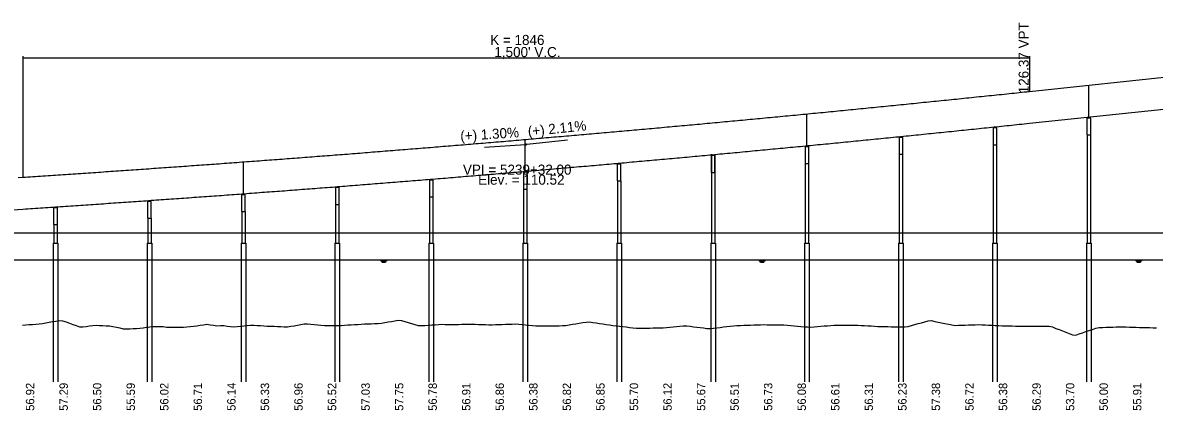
# Model space of a CAD drawing. Extents: x 2121671 to 2169879, y 557274 to 599957.
# Drawn here: x 2152750 to 2154437, y 595763 to 596342 of the extents above; entities that cross this region are included whole.
import ezdxf

# ---------------------------------------------------------------- set-up
doc = ezdxf.new("R2010")
doc.units = 0
for name, color, linetype in [('BR_CONCRETE', 7, 'Continuous'), ('BR_DETAILS', 7, 'Continuous'), ('BR_PRESTRESSED BEAM', 7, 'Continuous'), ('RD_DDB_GradeTX', 7, 'Continuous'), ('RD_DDB_Profile_Elev', 7, 'Continuous'), ('RD_DDB_Profile_EX', 7, 'Continuous'), ('RD_DDB_Profile_Lbl', 7, 'Continuous'), ('RD_DDB_Profile_PR', 7, 'Continuous'), ('RD_DDB_StripGrade', 7, 'Continuous'), ('RD_DDB_VCLbl', 7, 'Continuous')]:
    doc.layers.add(name, color=color, linetype=linetype)

msp = doc.modelspace()

# ---------------------------------------------------------------- linework, layer by layer
at = {"layer": 'BR_CONCRETE'}
for p, q in [((2154336.3, 596174.6), (2154336.3, 596013.1)), ((2154341.3, 596174.6), (2154341.3, 596013.1)), ((2154196.3, 596159.8), (2154196.3, 596013.1)), ((2154201.3, 596159.8), (2154201.3, 596013.1)), ((2153776.3, 596145.5), (2153776.3, 596013.1)), ((2153781.3, 596145.5), (2153781.3, 596013.1)), ((2153916.3, 596145.5), (2153916.3, 596013.1)), ((2153921.3, 596145.5), (2153921.3, 596013.1)), ((2154056.3, 596145.5), (2154056.3, 596013.1)), ((2154061.3, 596145.5), (2154061.3, 596013.1)), ((2153496.3, 596093.6), (2153496.3, 596013.1)), ((2153501.3, 596093.6), (2153501.3, 596013.1)), ((2153636.3, 596105.8), (2153636.3, 596013.1)), ((2153641.3, 596105.8), (2153641.3, 596013.1)), ((2153356.3, 596081.9), (2153356.3, 596013.1)), ((2153361.3, 596081.9), (2153361.3, 596013.1)), ((2153076.3, 596060.2), (2153076.3, 596013.1)), ((2153081.3, 596060.2), (2153081.3, 596013.1)), ((2153216.3, 596070.8), (2153216.3, 596013.1)), ((2153221.3, 596070.8), (2153221.3, 596013.1)), ((2152796.3, 596040.6), (2152796.3, 596013.1)), ((2152801.3, 596040.6), (2152801.3, 596013.1)), ((2152936.3, 596050.1), (2152936.3, 596013.1)), ((2152941.3, 596050.1), (2152941.3, 596013.1)), ((2152795.3, 596013.1), (2152795.3, 595805.8)), ((2152802.3, 596013.1), (2152802.3, 595805.8)), ((2152935.3, 596013.1), (2152935.3, 595805.8)), ((2152942.3, 596013.1), (2152942.3, 595805.8)), ((2153075.3, 596013.1), (2153075.3, 595805.8)), ((2153082.3, 596013.1), (2153082.3, 595805.8)), ((2153215.3, 596013.1), (2153215.3, 595805.8)), ((2153222.3, 596013.1), (2153222.3, 595805.8)), ((2153355.3, 596013.1), (2153355.3, 595805.8)), ((2153362.3, 596013.1), (2153362.3, 595805.8)), ((2153495.3, 596013.1), (2153495.3, 595805.8)), ((2153502.3, 596013.1), (2153502.3, 595805.8)), ((2153635.3, 596013.1), (2153635.3, 595805.8)), ((2153642.3, 596013.1), (2153642.3, 595805.8)), ((2153775.3, 596013.1), (2153775.3, 595805.8)), ((2153782.3, 596013.1), (2153782.3, 595805.8)), ((2153915.3, 596013.1), (2153915.3, 595805.8)), ((2153922.3, 596013.1), (2153922.3, 595805.8)), ((2154055.3, 596013.1), (2154055.3, 595805.8)), ((2154062.3, 596013.1), (2154062.3, 595805.8)), ((2154195.3, 596013.1), (2154195.3, 595805.8)), ((2154202.3, 596013.1), (2154202.3, 595805.8)), ((2154335.3, 596013.1), (2154335.3, 595805.8)), ((2154342.3, 596013.1), (2154342.3, 595805.8))]:
    msp.add_line(p, q, dxfattribs=at)
for points in [[(2154336.1, 596174.6), (2154341.6, 596174.6), (2154341.6, 596199.6), (2154336.1, 596199.6)], [(2154196.1, 596159.8), (2154201.6, 596159.8), (2154201.6, 596184.8), (2154196.1, 596184.8)], [(2153916.1, 596131.7), (2153921.6, 596131.7), (2153921.6, 596156.7), (2153916.1, 596156.7)], [(2154056.1, 596145.5), (2154061.6, 596145.5), (2154061.6, 596170.5), (2154056.1, 596170.5)], [(2153776.1, 596118.5), (2153781.6, 596118.5), (2153781.6, 596143.5), (2153776.1, 596143.5)], [(2153636.1, 596105.8), (2153641.6, 596105.8), (2153641.6, 596130.8), (2153636.1, 596130.8)], [(2153356.1, 596081.9), (2153361.6, 596081.9), (2153361.6, 596106.9), (2153356.1, 596106.9)], [(2153496.1, 596093.6), (2153501.6, 596093.6), (2153501.6, 596118.6), (2153496.1, 596118.6)], [(2153216.1, 596070.8), (2153221.6, 596070.8), (2153221.6, 596095.8), (2153216.1, 596095.8)], [(2152936.1, 596050.1), (2152941.6, 596050.1), (2152941.6, 596075.1), (2152936.1, 596075.1)], [(2153076.1, 596060.2), (2153081.6, 596060.2), (2153081.6, 596085.2), (2153076.1, 596085.2)], [(2152796.1, 596040.6), (2152801.6, 596040.6), (2152801.6, 596065.6), (2152796.1, 596065.6)]]:
    msp.add_lwpolyline(points, close=True, dxfattribs=at)
at = {"layer": 'BR_DETAILS'}
for points in [[(2154337.3, 596200.8), (2154338.3, 596200.8), (2154338.3, 596199.6), (2154337.3, 596199.6)], [(2154339.3, 596200.8), (2154340.3, 596200.8), (2154340.3, 596199.6), (2154339.3, 596199.6)], [(2154197.3, 596186.1), (2154198.3, 596186.1), (2154198.3, 596184.8), (2154197.3, 596184.8)], [(2154199.3, 596186.1), (2154200.3, 596186.1), (2154200.3, 596184.8), (2154199.3, 596184.8)], [(2153917.3, 596158), (2153918.3, 596158), (2153918.3, 596156.7), (2153917.3, 596156.7)], [(2153919.3, 596158), (2153920.3, 596158), (2153920.3, 596156.7), (2153919.3, 596156.7)], [(2154057.3, 596171.8), (2154058.3, 596171.8), (2154058.3, 596170.5), (2154057.3, 596170.5)], [(2154059.3, 596171.8), (2154060.3, 596171.8), (2154060.3, 596170.5), (2154059.3, 596170.5)], [(2153777.3, 596144.7), (2153778.3, 596144.7), (2153778.3, 596143.5), (2153777.3, 596143.5)], [(2153779.3, 596144.7), (2153780.3, 596144.7), (2153780.3, 596143.5), (2153779.3, 596143.5)], [(2153637.3, 596132), (2153638.3, 596132), (2153638.3, 596130.8), (2153637.3, 596130.8)], [(2153639.3, 596132), (2153640.3, 596132), (2153640.3, 596130.8), (2153639.3, 596130.8)], [(2153357.3, 596108.1), (2153358.3, 596108.1), (2153358.3, 596106.9), (2153357.3, 596106.9)], [(2153359.3, 596108.1), (2153360.3, 596108.1), (2153360.3, 596106.9), (2153359.3, 596106.9)], [(2153497.3, 596119.8), (2153498.3, 596119.8), (2153498.3, 596118.6), (2153497.3, 596118.6)], [(2153499.3, 596119.8), (2153500.3, 596119.8), (2153500.3, 596118.6), (2153499.3, 596118.6)], [(2153217.3, 596097), (2153218.3, 596097), (2153218.3, 596095.8), (2153217.3, 596095.8)], [(2153219.3, 596097), (2153220.3, 596097), (2153220.3, 596095.8), (2153219.3, 596095.8)], [(2152937.3, 596076.3), (2152938.3, 596076.3), (2152938.3, 596075.1), (2152937.3, 596075.1)], [(2152939.3, 596076.3), (2152940.3, 596076.3), (2152940.3, 596075.1), (2152939.3, 596075.1)], [(2153077.3, 596086.4), (2153078.3, 596086.4), (2153078.3, 596085.2), (2153077.3, 596085.2)], [(2153079.3, 596086.4), (2153080.3, 596086.4), (2153080.3, 596085.2), (2153079.3, 596085.2)], [(2152797.3, 596066.8), (2152798.3, 596066.8), (2152798.3, 596065.6), (2152797.3, 596065.6)], [(2152799.3, 596066.8), (2152800.3, 596066.8), (2152800.3, 596065.6), (2152799.3, 596065.6)]]:
    msp.add_lwpolyline(points, close=True, dxfattribs=at)
at = {"layer": 'BR_PRESTRESSED BEAM'}
for p, q in [((2154338.8, 596201), (2154338.8, 596248.5)), ((2154250.2, 596191.8), (2154543.2, 596222.7)), ((2153918.8, 596158.1), (2153918.8, 596205.6)), ((2153498.8, 596119.9), (2153498.8, 596167.4)), ((2153078.8, 596086.5), (2153078.8, 596134)), ((2152311.7, 596035.3), (2152750.2, 596063.8)), ((2152795.3, 596013.1), (2152802.3, 596013.1)), ((2152935.3, 596013.1), (2152942.3, 596013.1)), ((2153075.3, 596013.1), (2153082.3, 596013.1)), ((2153215.3, 596013.1), (2153222.3, 596013.1)), ((2153355.3, 596013.1), (2153362.3, 596013.1)), ((2153495.3, 596013.1), (2153502.3, 596013.1)), ((2153635.3, 596013.1), (2153642.3, 596013.1)), ((2153775.3, 596013.1), (2153782.3, 596013.1)), ((2153915.3, 596013.1), (2153922.3, 596013.1)), ((2154055.3, 596013.1), (2154062.3, 596013.1)), ((2154195.3, 596013.1), (2154202.3, 596013.1)), ((2154335.3, 596013.1), (2154342.3, 596013.1))]:
    msp.add_line(p, q, dxfattribs=at)
msp.add_spline([(2152750.2, 596063.8), (2152780.2, 596065.8), (2152810.2, 596067.8), (2152840.2, 596069.8), (2152870.2, 596071.8), (2152900.2, 596073.9), (2152930.2, 596076), (2152960.2, 596078.1), (2152990.2, 596080.2), (2153020.2, 596082.4), (2153050.2, 596084.5), (2153080.2, 596086.7), (2153110.2, 596089), (2153140.2, 596091.2), (2153170.2, 596093.5), (2153200.2, 596095.8), (2153230.2, 596098.1), (2153260.2, 596100.5), (2153290.2, 596102.9), (2153320.2, 596105.3), (2153350.2, 596107.7), (2153380.2, 596110.1), (2153410.2, 596112.6), (2153440.2, 596115.1), (2153470.2, 596117.6), (2153500.2, 596120.2), (2153530.2, 596122.8), (2153560.2, 596125.4), (2153590.2, 596128), (2153620.2, 596130.6), (2153650.2, 596133.3), (2153680.2, 596136), (2153710.2, 596138.7), (2153740.2, 596141.4), (2153770.2, 596144.2), (2153800.2, 596147), (2153830.2, 596149.8), (2153860.2, 596152.7), (2153890.2, 596155.5), (2153920.2, 596158.4), (2153950.2, 596161.3), (2153980.2, 596164.3), (2154010.2, 596167.2), (2154040.2, 596170.2), (2154070.2, 596173.2), (2154100.2, 596176.3), (2154130.2, 596179.3), (2154160.2, 596182.4), (2154190.2, 596185.5), (2154220.2, 596188.6), (2154250.2, 596191.8)], degree=3, dxfattribs=at)
at = {"layer": 'RD_DDB_GradeTX'}
for p, q in [((2153438.4, 596156.1), (2153499.2, 596160)), ((2153561.9, 596166.6), (2153501.2, 596160.2))]:
    msp.add_line(p, q, dxfattribs=at)
msp.add_circle((2153500.2, 596160.1), 1, dxfattribs=at)
at = {"layer": 'RD_DDB_Profile_Elev'}
for p, q in [((2151940.7, 596028.1), (2155629.7, 596028.1)), ((2151972, 595988.1), (2156334.9, 595988.1)), ((2153283, 595986.8), (2153293, 595986.8)), ((2153284.2, 595985.6), (2153291.7, 595985.6)), ((2153285.5, 595984.3), (2153290.5, 595984.3)), ((2153846.8, 595986.8), (2153856.8, 595986.8)), ((2153848, 595985.6), (2153855.5, 595985.6)), ((2153849.3, 595984.3), (2153854.3, 595984.3)), ((2154408.3, 595986.8), (2154418.3, 595986.8)), ((2154409.6, 595985.6), (2154417.1, 595985.6)), ((2154410.8, 595984.3), (2154415.8, 595984.3))]:
    msp.add_line(p, q, dxfattribs=at)
at = {"layer": 'RD_DDB_Profile_EX'}
for points in [[(2152749.5, 595890.4), (2152754.5, 595890.9), (2152759.5, 595891.3), (2152764.5, 595891.7), (2152769.5, 595892.2), (2152774.5, 595892.6), (2152779.5, 595893.2), (2152784.5, 595894), (2152789.5, 595894.9), (2152794.5, 595895.8), (2152799.5, 595896.6), (2152804.5, 595897.5), (2152809.5, 595897.1), (2152814.5, 595895.3), (2152819.5, 595893.5), (2152824.5, 595891.6), (2152829.5, 595889.8), (2152834.5, 595888), (2152839.5, 595888.1), (2152844.5, 595888.7), (2152849.5, 595889.3), (2152854.5, 595889.8), (2152859.5, 595890.4), (2152864.5, 595890.1), (2152869.5, 595889.9), (2152874.5, 595889.7), (2152879.5, 595889.4), (2152884.5, 595888.5), (2152889.5, 595887.4), (2152894.5, 595886.4), (2152899.5, 595885.3), (2152904.5, 595885.2), (2152909.5, 595885.3), (2152914.5, 595885.4), (2152919.5, 595885.5), (2152924.5, 595885.9), (2152929.5, 595886.6), (2152934.5, 595887.4), (2152939.5, 595888.1), (2152944.5, 595888.5), (2152949.5, 595888.4), (2152954.5, 595888.4), (2152959.5, 595888.3), (2152964.5, 595887.5), (2152969.5, 595887.6), (2152974.5, 595887.7), (2152979.5, 595887.7), (2152984.5, 595887.7), (2152989.5, 595887.7), (2152994.5, 595888.1), (2152999.5, 595888.4), (2153004.5, 595888.8), (2153009.5, 595889.5), (2153014.5, 595890.3), (2153019.5, 595891.2), (2153024.5, 595891.8), (2153029.5, 595891), (2153034.5, 595890.3), (2153039.5, 595889.6), (2153044.5, 595889.9), (2153049.5, 595889.9), (2153054.5, 595889.2), (2153059.5, 595888.6), (2153064.5, 595887.9), (2153069.5, 595888.3), (2153074.5, 595888.8), (2153079.5, 595889.4), (2153084.5, 595889.9), (2153089.5, 595890.4), (2153094.5, 595890.5), (2153099.5, 595890.1), (2153104.5, 595889.8), (2153109.5, 595889.5), (2153114.5, 595889.1), (2153119.5, 595889.1), (2153124.5, 595888.9), (2153129.5, 595888.6), (2153134.5, 595888.4), (2153139.5, 595888.1), (2153144.5, 595888), (2153149.5, 595888.8), (2153154.5, 595889.7), (2153159.5, 595890.6), (2153164.5, 595891.6), (2153169.5, 595892.5), (2153174.5, 595892.5), (2153179.5, 595892), (2153184.5, 595891.5), (2153189.5, 595890.9), (2153194.5, 595890.4)], [(2153194.5, 595890.4), (2153199.5, 595889.8), (2153204.5, 595889.8), (2153209.5, 595889.9), (2153214.5, 595890), (2153219.5, 595890.1), (2153224.5, 595890.2), (2153229.5, 595890.4), (2153234.5, 595890.8), (2153239.5, 595891.1), (2153244.5, 595891.4), (2153249.5, 595891.7), (2153254.5, 595892.1), (2153259.5, 595892.3), (2153264.5, 595892.5), (2153269.5, 595892.7), (2153274.5, 595892.9), (2153279.5, 595893.1), (2153284.5, 595893.4), (2153289.5, 595894.3), (2153294.5, 595895.3), (2153299.5, 595896.2), (2153304.5, 595897.1), (2153309.5, 595898.1), (2153314.5, 595897.3), (2153319.5, 595895.9), (2153324.5, 595894.4), (2153329.5, 595892.9), (2153334.5, 595891.4), (2153339.5, 595889.9), (2153344.5, 595889.8), (2153349.5, 595890.2), (2153354.5, 595890.5), (2153359.5, 595890.8), (2153364.5, 595891.1), (2153369.5, 595891.4), (2153374.5, 595891.8), (2153379.5, 595891.5), (2153384.5, 595891.6), (2153389.5, 595891.6), (2153394.5, 595891.7), (2153399.5, 595891.7), (2153404.5, 595891.8), (2153409.5, 595891.8), (2153414.5, 595892.1), (2153419.5, 595892), (2153424.5, 595891.8), (2153429.5, 595891.7), (2153434.5, 595891.5), (2153439.5, 595891.4), (2153444.5, 595891.2), (2153449.5, 595891.1), (2153454.5, 595891.3), (2153459.5, 595891.4), (2153464.5, 595891.6), (2153469.5, 595891.8), (2153474.5, 595892), (2153479.5, 595892.2), (2153484.5, 595892.3), (2153489.5, 595892), (2153494.5, 595891.5), (2153499.5, 595891.1), (2153504.5, 595890.6), (2153509.5, 595890.2), (2153514.5, 595889.7), (2153519.5, 595889.3), (2153524.5, 595889.3), (2153529.5, 595889.3), (2153534.5, 595889.4), (2153539.5, 595889.5), (2153544.5, 595889.6), (2153549.5, 595889.7), (2153554.5, 595889.8), (2153559.5, 595890.1), (2153564.5, 595891), (2153569.5, 595891.8), (2153574.5, 595892.6), (2153579.5, 595893.4), (2153584.5, 595894.3), (2153589.5, 595895.1), (2153594.5, 595895.4), (2153599.5, 595894.6), (2153604.5, 595893.9), (2153609.5, 595893.1), (2153614.5, 595892.3), (2153619.5, 595891.5), (2153624.5, 595890.8), (2153629.5, 595890.2), (2153634.5, 595889.6), (2153639.5, 595889), (2153644.5, 595888.4), (2153649.5, 595887.8), (2153654.5, 595887.1), (2153659.5, 595886.5), (2153664.5, 595885.9), (2153669.5, 595886), (2153674.5, 595886.1), (2153679.5, 595886.1), (2153684.5, 595886.2), (2153689.5, 595886.3), (2153694.5, 595886.3)], [(2153694.5, 595886.3), (2153699.5, 595886.4), (2153704.5, 595886.7), (2153709.5, 595887.2), (2153714.5, 595887.7), (2153719.5, 595888.2), (2153724.5, 595888.7), (2153729.5, 595889.2), (2153734.5, 595889.7), (2153739.5, 595889.4), (2153744.5, 595888.8), (2153749.5, 595888.2), (2153754.5, 595887.5), (2153759.5, 595886.9), (2153764.5, 595886.3), (2153769.5, 595885.6), (2153774.5, 595885.6), (2153779.5, 595886.2), (2153784.5, 595886.7), (2153789.5, 595887.2), (2153794.5, 595887.8), (2153799.5, 595888.3), (2153804.5, 595888.8), (2153809.5, 595889.4), (2153814.5, 595889.9), (2153819.5, 595890.1), (2153824.5, 595890.3), (2153829.5, 595890.5), (2153834.5, 595890.7), (2153839.5, 595890.8), (2153844.5, 595891), (2153849.5, 595891.2), (2153854.5, 595891.3), (2153859.5, 595891.2), (2153864.5, 595891.2), (2153869.5, 595891.1), (2153874.5, 595891.1), (2153879.5, 595891), (2153884.5, 595890.9), (2153889.5, 595890.7), (2153894.5, 595890.2), (2153899.5, 595889.7), (2153904.5, 595889.2), (2153909.5, 595888.7), (2153914.5, 595888.2), (2153919.5, 595887.8), (2153924.5, 595887.6), (2153929.5, 595888), (2153934.5, 595888.4), (2153939.5, 595888.9), (2153944.5, 595889.3), (2153949.5, 595889.7), (2153954.5, 595890.2), (2153959.5, 595890.5), (2153964.5, 595890.5), (2153969.5, 595890.5), (2153974.5, 595890.5), (2153979.5, 595890.5), (2153984.5, 595890.5), (2153989.5, 595890.6), (2153994.5, 595890.6), (2153999.5, 595890.2), (2154004.5, 595889.9), (2154009.5, 595889.6), (2154014.5, 595889.3), (2154019.5, 595888.9), (2154024.5, 595888.6), (2154029.5, 595888.3), (2154034.5, 595888.3), (2154039.5, 595888.3), (2154044.5, 595888.2), (2154049.5, 595888.2), (2154054.5, 595888.2), (2154059.5, 595888.2), (2154064.5, 595888.2), (2154069.5, 595888.7), (2154074.5, 595890.1), (2154079.5, 595891.5), (2154084.5, 595892.9), (2154089.5, 595894.2), (2154094.5, 595895.6), (2154099.5, 595897), (2154104.5, 595897.3), (2154109.5, 595896.2), (2154114.5, 595895.2), (2154119.5, 595894.1), (2154124.5, 595893), (2154129.5, 595892), (2154134.5, 595890.9), (2154139.5, 595890.2), (2154144.5, 595890.4), (2154149.5, 595890.5), (2154154.5, 595890.7), (2154159.5, 595890.8), (2154164.5, 595891), (2154169.5, 595891.1), (2154174.5, 595891.3), (2154179.5, 595891), (2154184.5, 595890.8), (2154189.5, 595890.5), (2154194.5, 595890.3)], [(2154194.5, 595890.3), (2154199.5, 595890), (2154204.5, 595889.8), (2154209.5, 595889.6), (2154214.5, 595889.4), (2154219.5, 595889.4), (2154224.5, 595889.3), (2154229.5, 595889.2), (2154234.5, 595889.2), (2154239.5, 595889.1), (2154244.5, 595889.1), (2154249.5, 595889.1), (2154254.5, 595889), (2154259.5, 595889), (2154264.5, 595888.9), (2154269.5, 595888.9), (2154274.5, 595888.8), (2154279.5, 595888.8), (2154284.5, 595887.8), (2154289.5, 595885.8), (2154294.5, 595883.9), (2154299.5, 595882), (2154304.5, 595880.1), (2154309.5, 595878.2), (2154314.5, 595876.3), (2154319.5, 595875.8), (2154324.5, 595877.5), (2154329.5, 595879.2), (2154334.5, 595880.9), (2154339.5, 595882.6), (2154344.5, 595884.3), (2154349.5, 595886), (2154354.5, 595887.1), (2154359.5, 595887.2), (2154364.5, 595887.4), (2154369.5, 595887.5), (2154374.5, 595887.6), (2154379.5, 595887.8), (2154384.5, 595887.9), (2154389.5, 595888), (2154394.5, 595887.8), (2154399.5, 595887.7), (2154404.5, 595887.5), (2154409.5, 595887.3), (2154414.5, 595887.2), (2154419.5, 595887), (2154424.5, 595886.8), (2154429.5, 595886.8), (2154434.5, 595886.7), (2154439.5, 595886.6)]]:
    msp.add_lwpolyline(points, dxfattribs=at)
at = {"layer": 'RD_DDB_Profile_PR'}
for p, q in [((2154250.2, 596239.3), (2154693.2, 596286.1)), ((2152743.2, 596110.9), (2152750.2, 596111.3))]:
    msp.add_line(p, q, dxfattribs=at)
msp.add_spline([(2152750.2, 596111.3), (2152780.2, 596113.3), (2152810.2, 596115.3), (2152840.2, 596117.3), (2152870.2, 596119.3), (2152900.2, 596121.4), (2152930.2, 596123.5), (2152960.2, 596125.6), (2152990.2, 596127.7), (2153020.2, 596129.9), (2153050.2, 596132), (2153080.2, 596134.3), (2153110.2, 596136.5), (2153140.2, 596138.7), (2153170.2, 596141), (2153200.2, 596143.3), (2153230.2, 596145.6), (2153260.2, 596148), (2153290.2, 596150.4), (2153320.2, 596152.8), (2153350.2, 596155.2), (2153380.2, 596157.7), (2153410.2, 596160.1), (2153440.2, 596162.6), (2153470.2, 596165.1), (2153500.2, 596167.7), (2153530.2, 596170.3), (2153560.2, 596172.9), (2153590.2, 596175.5), (2153620.2, 596178.1), (2153650.2, 596180.8), (2153680.2, 596183.5), (2153710.2, 596186.2), (2153740.2, 596188.9), (2153770.2, 596191.7), (2153800.2, 596194.5), (2153830.2, 596197.3), (2153860.2, 596200.2), (2153890.2, 596203), (2153920.2, 596205.9), (2153950.2, 596208.8), (2153980.2, 596211.8), (2154010.2, 596214.7), (2154040.2, 596217.7), (2154070.2, 596220.7), (2154100.2, 596223.8), (2154130.2, 596226.8), (2154160.2, 596229.9), (2154190.2, 596233), (2154220.2, 596236.1), (2154250.2, 596239.3)], degree=3, dxfattribs=at)
at = {"layer": 'RD_DDB_VCLbl'}
for p, q in [((2152750.2, 596291.8), (2152750.2, 596111.3)), ((2154250.2, 596291.8), (2154250.2, 596239.3)), ((2152750.2, 596289.3), (2154250.2, 596289.3))]:
    msp.add_line(p, q, dxfattribs=at)

# ---------------------------------------------------------------- texts
at = {"layer": 'RD_DDB_GradeTX'}
for s, rotation, p in [('(+) 2.11%', 6.0299, (2153503.6, 596172.1)), ('(+) 1.30%', 3.7187, (2153402.6, 596165.3))]:
    msp.add_text(s, height=15, rotation=rotation, dxfattribs=at).set_placement(p)
at = {"layer": 'RD_DDB_Profile_Lbl'}
for s, p in [('VPI = 5239+32.00', (2153406.1, 596115.1)), ('Elev. = 110.52', (2153428.7, 596100.1))]:
    msp.add_text(s, height=15, dxfattribs=at).set_placement(p)
at = {"layer": 'RD_DDB_StripGrade'}
for s, height, p in [('126.37 VPT', 15, (2154249.2, 596236.5)), ('56.92', 12.5, (2152767.2, 595762.7)), ('57.29', 12.5, (2152817.2, 595762.7)), ('56.50', 12.5, (2152867.2, 595762.7)), ('55.59', 12.5, (2152917.2, 595762.7)), ('56.02', 12.5, (2152967.2, 595762.7)), ('56.71', 12.5, (2153017.2, 595762.7)), ('56.14', 12.5, (2153067.2, 595762.7)), ('56.33', 12.5, (2153117.2, 595762.7)), ('56.96', 12.5, (2153167.2, 595762.7)), ('56.52', 12.5, (2153217.2, 595762.7)), ('57.03', 12.5, (2153267.2, 595762.7)), ('57.75', 12.5, (2153317.2, 595762.7)), ('56.78', 12.5, (2153367.2, 595762.7)), ('56.91', 12.5, (2153417.2, 595762.7)), ('56.86', 12.5, (2153467.2, 595762.7)), ('56.38', 12.5, (2153517.2, 595762.7)), ('56.82', 12.5, (2153567.2, 595762.7)), ('56.85', 12.5, (2153617.2, 595762.7)), ('55.70', 12.5, (2153667.2, 595762.7)), ('56.12', 12.5, (2153717.2, 595762.7)), ('55.67', 12.5, (2153767.2, 595762.7)), ('56.51', 12.5, (2153817.2, 595762.7)), ('56.73', 12.5, (2153867.2, 595762.7)), ('56.08', 12.5, (2153917.2, 595762.7)), ('56.61', 12.5, (2153967.2, 595762.7)), ('56.31', 12.5, (2154017.2, 595762.7)), ('56.23', 12.5, (2154067.2, 595762.7)), ('57.38', 12.5, (2154117.2, 595762.7)), ('56.72', 12.5, (2154167.2, 595762.7)), ('56.38', 12.5, (2154217.2, 595762.7)), ('56.29', 12.5, (2154267.2, 595762.7)), ('53.70', 12.5, (2154317.2, 595762.7)), ('56.00', 12.5, (2154367.2, 595762.7)), ('55.91', 12.5, (2154417.2, 595762.7))]:
    msp.add_text(s, height=height, rotation=90, dxfattribs=at).set_placement(p)
at = {"layer": 'RD_DDB_VCLbl'}
for s, p in [('K = 1846', (2153446.7, 596308.6)), ("1,500' V.C.", (2153452.9, 596290.5))]:
    msp.add_text(s, height=15, dxfattribs=at).set_placement(p)

doc.saveas('drawing.dxf')
